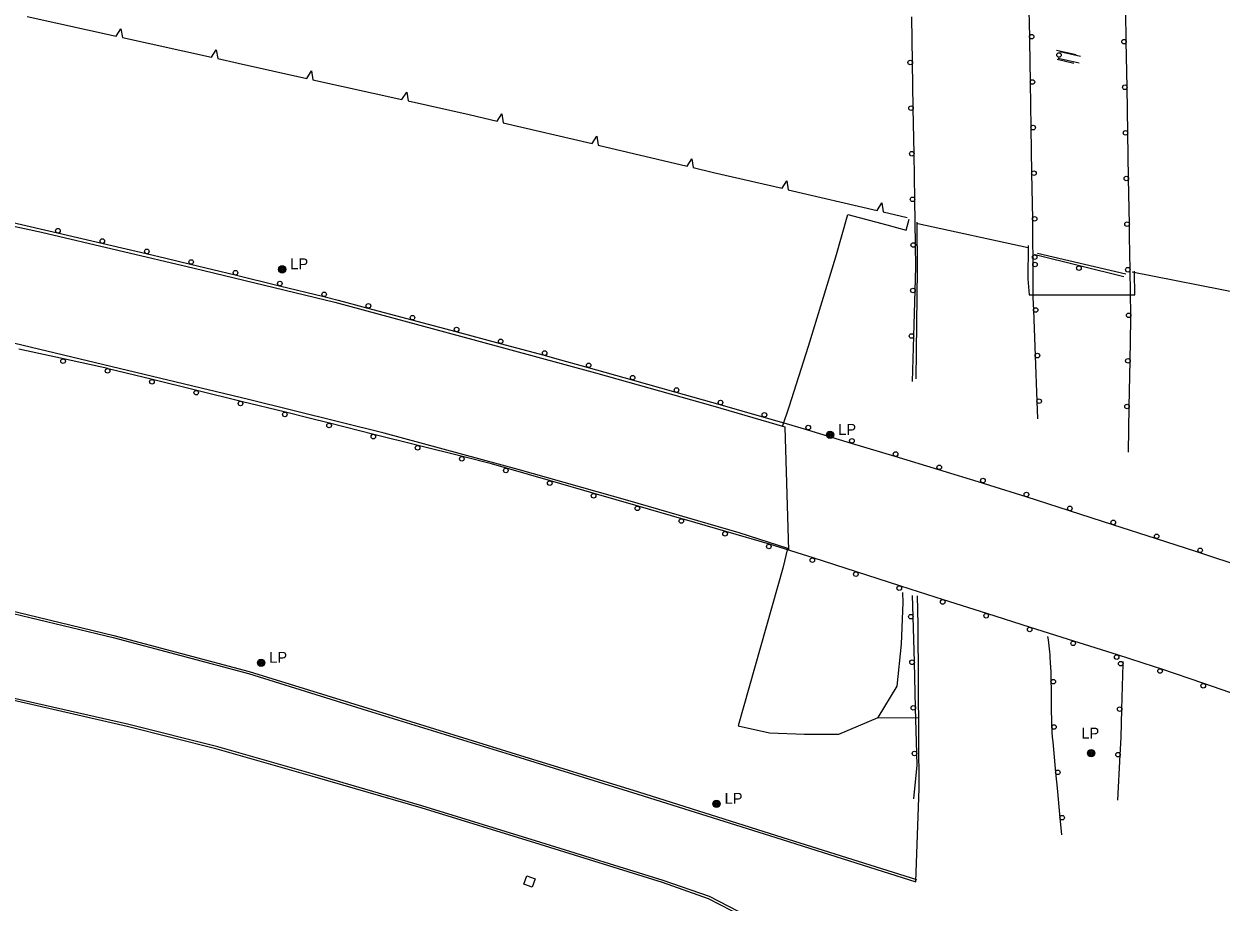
# Model space of a CAD drawing. Extents: x 2402803 to 2427059, y 6985292 to 6997652.
# Drawn here: x 2413911 to 2414436, y 6991229 to 6991614 of the extents above; entities that cross this region are included whole.
import ezdxf

# ---------------------------------------------------------------- set-up
doc = ezdxf.new("R2010")
doc.units = 0
for name, color, linetype in [('p_drainage riprap', 7, 'Continuous'), ('p_dtm retaining wall', 7, 'Continuous'), ('p_dtm sidewalk', 7, 'Continuous'), ('p_road - paved curb', 7, 'Continuous'), ('p_road bridge end', 7, 'Continuous'), ('p_road conc barrier', 7, 'Continuous'), ('p_road guard rails', 7, 'Continuous'), ('p_utility manhole', 7, 'Continuous')]:
    doc.layers.add(name, color=color, linetype=linetype)

msp = doc.modelspace()

# ---------------------------------------------------------------- linework, layer by layer
at = {"layer": 'p_drainage riprap'}
for points in [[(2414243.49, 6991437.79), (2414246.43, 6991446.34), (2414254.83, 6991472.89), (2414266.9, 6991512.05), (2414272.09, 6991530.62), (2414289.18, 6991526.08), (2414297.66, 6991523.82), (2414298.92, 6991528.58)], [(2414245.7, 6991384.28), (2414243.6, 6991375.68), (2414224.09, 6991306.43), (2414237.72, 6991303.37), (2414253.14, 6991302.87), (2414268.2, 6991302.82), (2414285.44, 6991310.17), (2414293.76, 6991323.88), (2414295.59, 6991342.27), (2414296.28, 6991360.5), (2414296.14, 6991364.88)]]:
    msp.add_lwpolyline(points, dxfattribs=at)
at = {"layer": 'p_dtm retaining wall'}
for p, q in [((2413912.38, 6991617.49), (2413951.44, 6991608.87)), ((2413954.15, 6991608.27), (2413993.21, 6991599.66)), ((2414037.66, 6991589.76), (2414076.69, 6991581.04)), ((2414121.09, 6991570.92), (2414160.02, 6991561.73)), ((2414162.71, 6991561.09), (2414201.63, 6991551.89)), ((2414245.98, 6991541.54), (2414284.94, 6991532.48)), ((2414287.64, 6991531.85), (2414298.12, 6991529.41)), ((2414355.29, 6991513.78), (2414393.94, 6991504.71))]:
    msp.add_line(p, q, dxfattribs=at)
for points in [[(2413951.44, 6991608.87), (2413953.51, 6991612.13), (2413954.15, 6991608.27)], [(2413993.21, 6991599.66), (2413995.28, 6991602.92), (2413995.91, 6991599.06)], [(2413995.91, 6991599.06), (2414004.92, 6991597.07), (2414034.95, 6991590.36)], [(2414034.95, 6991590.36), (2414037.03, 6991593.62), (2414037.66, 6991589.76)], [(2414076.69, 6991581.04), (2414078.77, 6991584.29), (2414079.4, 6991580.43)], [(2414079.4, 6991580.43), (2414106.13, 6991574.46), (2414118.4, 6991571.56)], [(2414118.4, 6991571.56), (2414120.52, 6991574.79), (2414121.09, 6991570.92)], [(2414160.02, 6991561.73), (2414162.14, 6991564.96), (2414162.71, 6991561.09)], [(2414201.63, 6991551.89), (2414203.75, 6991555.12), (2414204.33, 6991551.26)], [(2414204.33, 6991551.26), (2414213.28, 6991549.14), (2414243.28, 6991542.16)], [(2414243.28, 6991542.16), (2414245.39, 6991545.4), (2414245.98, 6991541.54)], [(2414284.94, 6991532.48), (2414287.05, 6991535.71), (2414287.64, 6991531.85)]]:
    msp.add_lwpolyline(points, dxfattribs=at)
at = {"layer": 'p_dtm sidewalk'}
msp.add_lwpolyline([(2414285.33, 6991310.12), (2414303.18, 6991309.97)], dxfattribs=at)
at = {"layer": 'p_road - paved curb'}
for points in [[(2413453.34, 6991608.46), (2413509.85, 6991599.67), (2413578.7, 6991589.29), (2413645.86, 6991577.8), (2413715.9, 6991564.99), (2413780.65, 6991551.96), (2413855.53, 6991536.52), (2413918.66, 6991522.88), (2413985.54, 6991507.12), (2414047.19, 6991492.25), (2414109.4, 6991475.44), (2414161.57, 6991461.23), (2414212.88, 6991446.72), (2414244.43, 6991437.52)], [(2414363.5, 6991602.67), (2414372.16, 6991600.87)], [(2414371.2, 6991596.84), (2414363.78, 6991598.66)], [(2414245.83, 6991384.24), (2414224.52, 6991391.1), (2414175.69, 6991405.24), (2414127.62, 6991418.9), (2414068.94, 6991434.75), (2414009.43, 6991449.6), (2413956.34, 6991462.24), (2413903.4, 6991474.96), (2413851.74, 6991485.33), (2413797.83, 6991495.68), (2413736.61, 6991506.25), (2413672.73, 6991516.4), (2413613.14, 6991524.23), (2413535.08, 6991532.86), (2413481.44, 6991537), (2413453.89, 6991539.47)], [(2414302.11, 6991458.63), (2414302.57, 6991506.69), (2414302.45, 6991527.35)], [(2414351.14, 6991517.03), (2414351.03, 6991502.5), (2414351.6, 6991495.39), (2414373.91, 6991495.43), (2414397.85, 6991495.5), (2414397.79, 6991505.37), (2414397.78, 6991505.78)], [(2413454.02, 6991406.53), (2413496.39, 6991406.37), (2413542.63, 6991405.58), (2413589.38, 6991402.88), (2413647.61, 6991398.85), (2413698.58, 6991392.94), (2413761.8, 6991384.22), (2413820.56, 6991374.6), (2413884.46, 6991361.97), (2413950.32, 6991346.15), (2414009.68, 6991330.33), (2414061.69, 6991314.17), (2414124.33, 6991294.84), (2414180.4, 6991277.52), (2414240.81, 6991258.42), (2414302.17, 6991239.11)], [(2413454.02, 6991405.53), (2413496.38, 6991405.37), (2413542.59, 6991404.58), (2413589.32, 6991401.88), (2413647.52, 6991397.85), (2413698.45, 6991391.95), (2413761.65, 6991383.23), (2413820.38, 6991373.62), (2413884.25, 6991360.99), (2413950.07, 6991345.18), (2414009.4, 6991329.37), (2414061.39, 6991313.21), (2414124.04, 6991293.88), (2414180.1, 6991276.57), (2414240.51, 6991257.47), (2414301.87, 6991238.16)], [(2414277.03, 6991186.65), (2414260.39, 6991202.15), (2414237.15, 6991218.35), (2414211.46, 6991231.59), (2414191.18, 6991238.74), (2414137.57, 6991255.4), (2414085.36, 6991271.45), (2414038.86, 6991284.99), (2413995.91, 6991297.26), (2413956.43, 6991307.23), (2413906.16, 6991318.65), (2413847, 6991330.36), (2413820.95, 6991334.68), (2413796.72, 6991338.96), (2413745.99, 6991346.15), (2413683.54, 6991352.92), (2413629.83, 6991356.54), (2413587.38, 6991358.99), (2413519.22, 6991360.65), (2413455.96, 6991360.73)], [(2414301.87, 6991238.16), (2414303.39, 6991279.16), (2414303.25, 6991300.81), (2414302.88, 6991350.73), (2414302.65, 6991363.5)], [(2414276.35, 6991185.92), (2414259.76, 6991201.37), (2414236.63, 6991217.49), (2414211.06, 6991230.67), (2414190.87, 6991237.79), (2414137.27, 6991254.44), (2414085.07, 6991270.49), (2414038.58, 6991284.03), (2413995.65, 6991296.29), (2413956.2, 6991306.26), (2413905.95, 6991317.67), (2413846.82, 6991329.38), (2413820.78, 6991333.69), (2413817.11, 6991334.34)]]:
    msp.add_lwpolyline(points, dxfattribs=at)
at = {"layer": 'p_road bridge end'}
for points in [[(2414302.75, 6991526.73), (2414351.16, 6991516.24)], [(2414396.66, 6991505.5), (2414445.67, 6991495.81)], [(2414244.42, 6991437.36), (2414246.08, 6991383.47)]]:
    msp.add_lwpolyline(points, dxfattribs=at)
msp.add_lwpolyline([(2414135.03, 6991239.48), (2414133.71, 6991235.77), (2414130.13, 6991237.04), (2414131.45, 6991240.75)], close=True, dxfattribs=at)
at = {"layer": 'p_road conc barrier'}
for p, q in [((2414364.96, 6991602.07), (2414374.13, 6991600.02)), ((2414364.31, 6991599.14), (2414373.48, 6991597.09))]:
    msp.add_line(p, q, dxfattribs=at)
msp.add_circle((2414364.63, 6991600.6), 1, dxfattribs=at)
at = {"layer": 'p_road guard rails'}
for p, q in [((2414351.24, 6991628.59), (2414351.67, 6991608.59)), ((2414300.45, 6991597.31), (2414300.12, 6991617.31)), ((2414394.49, 6991586.45), (2414394.16, 6991606.45)), ((2414300.78, 6991577.32), (2414300.45, 6991597.31)), ((2414352.01, 6991588.74), (2414352.33, 6991568.75)), ((2414394.82, 6991566.46), (2414394.49, 6991586.45)), ((2414301.12, 6991557.32), (2414300.78, 6991577.32)), ((2414352.33, 6991568.75), (2414352.65, 6991548.75)), ((2414395.16, 6991546.46), (2414394.82, 6991566.46)), ((2414301.45, 6991537.32), (2414301.12, 6991557.32)), ((2414352.65, 6991548.75), (2414352.97, 6991528.75)), ((2414395.49, 6991526.46), (2414395.16, 6991546.46)), ((2414301.78, 6991517.33), (2414301.45, 6991537.32)), ((2413906.19, 6991527.12), (2413925.66, 6991522.58)), ((2413925.66, 6991522.58), (2413945.14, 6991518.04)), ((2413945.14, 6991518.04), (2413964.61, 6991513.5)), ((2414354.21, 6991512.95), (2414353.94, 6991513.02)), ((2414373.62, 6991508.13), (2414354.21, 6991512.95)), ((2413984.06, 6991508.86), (2414003.5, 6991504.14)), ((2414393.03, 6991503.3), (2414373.62, 6991508.13)), ((2414396.17, 6991486.47), (2414395.83, 6991506.47)), ((2414003.5, 6991504.14), (2414022.93, 6991499.43)), ((2414022.93, 6991499.43), (2414042.37, 6991494.71)), ((2414301.01, 6991477.37), (2414301.62, 6991497.34)), ((2414061.72, 6991489.67), (2414081.04, 6991484.49)), ((2414353.44, 6991488.76), (2414354.18, 6991468.77)), ((2414081.04, 6991484.49), (2414100.35, 6991479.3)), ((2414100.35, 6991479.3), (2414119.67, 6991474.12)), ((2414300.39, 6991457.39), (2414301.01, 6991477.37)), ((2413928.36, 6991467.34), (2413908.82, 6991471.6)), ((2414119.67, 6991474.12), (2414138.99, 6991468.93)), ((2414354.18, 6991468.77), (2414354.93, 6991448.78)), ((2414395.47, 6991446.48), (2414395.85, 6991466.47)), ((2413967.31, 6991458.3), (2413947.9, 6991463.07)), ((2414158.25, 6991463.57), (2414177.5, 6991458.14)), ((2413986.73, 6991453.52), (2413967.31, 6991458.3)), ((2414177.5, 6991458.14), (2414196.75, 6991452.72)), ((2414006.15, 6991448.75), (2413986.73, 6991453.52)), ((2414025.57, 6991443.98), (2414006.15, 6991448.75)), ((2414196.75, 6991452.72), (2414216, 6991447.3)), ((2414354.93, 6991448.78), (2414355.22, 6991441.06)), ((2414216, 6991447.3), (2414235.25, 6991441.88)), ((2414395.09, 6991426.48), (2414395.47, 6991446.48)), ((2414064.37, 6991434.27), (2414044.98, 6991439.15)), ((2414083.77, 6991429.38), (2414064.37, 6991434.27)), ((2414254.46, 6991436.29), (2414273.59, 6991430.47)), ((2414103.16, 6991424.5), (2414083.77, 6991429.38)), ((2414273.59, 6991430.47), (2414292.73, 6991424.66)), ((2414292.73, 6991424.66), (2414311.87, 6991418.85)), ((2414141.72, 6991413.86), (2414122.5, 6991419.39)), ((2414311.87, 6991418.85), (2414331.01, 6991413.04)), ((2414160.94, 6991408.32), (2414141.72, 6991413.86)), ((2414180.15, 6991402.79), (2414160.94, 6991408.32)), ((2414350.06, 6991406.97), (2414369.09, 6991400.85)), ((2414199.37, 6991397.25), (2414180.15, 6991402.79)), ((2414369.09, 6991400.85), (2414388.13, 6991394.72)), ((2414237.78, 6991386.07), (2414218.58, 6991391.67)), ((2414388.13, 6991394.72), (2414407.17, 6991388.6)), ((2414426.2, 6991382.46), (2414445.18, 6991376.2)), ((2414275.9, 6991373.95), (2414256.86, 6991380.08)), ((2414294.93, 6991367.83), (2414275.9, 6991373.95)), ((2414300.72, 6991354.38), (2414300.47, 6991363.56)), ((2414333.05, 6991355.71), (2414313.99, 6991361.76)), ((2414301.26, 6991334.38), (2414300.72, 6991354.38)), ((2414352.11, 6991349.67), (2414333.05, 6991355.71)), ((2414371.18, 6991343.62), (2414352.11, 6991349.67)), ((2414390.24, 6991337.57), (2414371.18, 6991343.62)), ((2414301.79, 6991314.39), (2414301.26, 6991334.38)), ((2414392.22, 6991313.75), (2414392.71, 6991333.74)), ((2414392.71, 6991333.74), (2414392.74, 6991334.75)), ((2414428.19, 6991325), (2414409.28, 6991331.46)), ((2414447.11, 6991318.54), (2414428.19, 6991325)), ((2414302.33, 6991294.4), (2414301.79, 6991314.39)), ((2414390.47, 6991273.87), (2414391.51, 6991293.79)), ((2414365.03, 6991266.12), (2414365.73, 6991258.69))]:
    msp.add_line(p, q, dxfattribs=at)
for points in [[(2414394.16, 6991606.45), (2414394.12, 6991608.76), (2414393.81, 6991626.45)], [(2414351.67, 6991608.59), (2414351.71, 6991606.66), (2414351.73, 6991606.69), (2414352.01, 6991588.74)], [(2414352.97, 6991528.75), (2414353.08, 6991521.67), (2414353.15, 6991508.75)], [(2414395.83, 6991506.47), (2414395.58, 6991520.97), (2414395.49, 6991526.46)], [(2414301.62, 6991497.34), (2414301.94, 6991507.66), (2414301.78, 6991517.33)], [(2413964.61, 6991513.5), (2413973.17, 6991511.51), (2413984.06, 6991508.86)], [(2414353.15, 6991508.75), (2414353.23, 6991494.29), (2414353.44, 6991488.76)], [(2414042.37, 6991494.71), (2414048.69, 6991493.17), (2414061.72, 6991489.67)], [(2414395.85, 6991466.47), (2414396.2, 6991484.53), (2414396.17, 6991486.47)], [(2413947.9, 6991463.07), (2413947.82, 6991463.09), (2413928.36, 6991467.34)], [(2414138.99, 6991468.93), (2414143.47, 6991467.73), (2414158.25, 6991463.57)], [(2414044.98, 6991439.15), (2414035.98, 6991441.42), (2414025.57, 6991443.98)], [(2414235.25, 6991441.88), (2414246.14, 6991438.81), (2414254.46, 6991436.29)], [(2414122.5, 6991419.39), (2414115.95, 6991421.28), (2414103.16, 6991424.5)], [(2414331.01, 6991413.04), (2414334.21, 6991412.07), (2414350.06, 6991406.97)], [(2414218.58, 6991391.67), (2414200.57, 6991396.91), (2414199.37, 6991397.25)], [(2414256.86, 6991380.08), (2414242.43, 6991384.72), (2414237.78, 6991386.07)], [(2414407.17, 6991388.6), (2414424.48, 6991383.03), (2414426.2, 6991382.46)], [(2414313.99, 6991361.76), (2414299.37, 6991366.4), (2414294.93, 6991367.83)], [(2414359.61, 6991345.7), (2414359.72, 6991344.95), (2414359.84, 6991344.21), (2414360.04, 6991342.84), (2414360.21, 6991341.51), (2414360.36, 6991340.22), (2414360.49, 6991338.97), (2414360.6, 6991337.75), (2414360.7, 6991336.57), (2414360.85, 6991334.27), (2414360.96, 6991332.12), (2414361.04, 6991330.09), (2414361.1, 6991328.18), (2414361.14, 6991326.39), (2414361.14, 6991325.84)], [(2414409.28, 6991331.46), (2414406.51, 6991332.41), (2414390.24, 6991337.57)], [(2414361.14, 6991325.84), (2414361.18, 6991323.03), (2414361.22, 6991317.13), (2414361.27, 6991312.71), (2414361.34, 6991309.39), (2414361.42, 6991306.91), (2414361.47, 6991305.91)], [(2414391.51, 6991293.79), (2414391.91, 6991301.4), (2414392.22, 6991313.75)], [(2414361.47, 6991305.91), (2414361.51, 6991305.05), (2414361.58, 6991303.66), (2414361.72, 6991301.58), (2414361.9, 6991299.5), (2414363.17, 6991286.01)], [(2414301.05, 6991274.47), (2414302.47, 6991289.26), (2414302.33, 6991294.4)], [(2414363.17, 6991286.01), (2414363.81, 6991279.09), (2414365.03, 6991266.12)]]:
    msp.add_lwpolyline(points, dxfattribs=at)
for centre in [(2414352.67, 6991608.62), (2414393.16, 6991606.44), (2414299.45, 6991597.3), (2414353.01, 6991588.76), (2414393.49, 6991586.44), (2414299.78, 6991577.3), (2414353.33, 6991568.76), (2414393.82, 6991566.44), (2414300.12, 6991557.3), (2414353.65, 6991548.76), (2414394.16, 6991546.44), (2414300.45, 6991537.31), (2414353.97, 6991528.77), (2414394.49, 6991526.45), (2413925.89, 6991523.55), (2413945.36, 6991519.02), (2414300.78, 6991517.31), (2413964.84, 6991514.48), (2414353.97, 6991511.98), (2413984.3, 6991509.84), (2414354.15, 6991508.76), (2414373.38, 6991507.16), (2414394.83, 6991506.45), (2414003.73, 6991505.12), (2414023.17, 6991500.4), (2414042.6, 6991495.68), (2414300.62, 6991497.37), (2414061.98, 6991490.64), (2414081.3, 6991485.45), (2414354.44, 6991488.79), (2414395.17, 6991486.45), (2414100.61, 6991480.27), (2414119.93, 6991475.08), (2414300.01, 6991477.4), (2414139.24, 6991469.9), (2414355.18, 6991468.81), (2413928.14, 6991466.36), (2414158.52, 6991464.53), (2414394.85, 6991466.49), (2413947.66, 6991462.1), (2414177.77, 6991459.11), (2413967.08, 6991457.33), (2414197.02, 6991453.68), (2413986.5, 6991452.55), (2414005.91, 6991447.78), (2414216.27, 6991448.26), (2414355.93, 6991448.82), (2414025.33, 6991443.01), (2414235.53, 6991442.84), (2414394.47, 6991446.5), (2414044.74, 6991438.18), (2414254.75, 6991437.24), (2414064.13, 6991433.3), (2414083.52, 6991428.41), (2414273.88, 6991431.43), (2414102.92, 6991423.53), (2414293.02, 6991425.62), (2414122.22, 6991418.43), (2414312.16, 6991419.81), (2414141.44, 6991412.9), (2414331.3, 6991414), (2414160.66, 6991407.36), (2414350.36, 6991407.92), (2414179.88, 6991401.83), (2414369.4, 6991401.8), (2414199.1, 6991396.29), (2414388.44, 6991395.68), (2414218.3, 6991390.71), (2414237.5, 6991385.11), (2414407.47, 6991389.55), (2414426.51, 6991383.41), (2414256.55, 6991379.13), (2414275.59, 6991373), (2414294.63, 6991366.88), (2414313.69, 6991360.81), (2414299.72, 6991354.35), (2414332.75, 6991354.76), (2414351.81, 6991348.71), (2414370.87, 6991342.67), (2414300.26, 6991334.36), (2414389.93, 6991336.62), (2414391.72, 6991333.76), (2414408.95, 6991330.52), (2414362.14, 6991325.86), (2414427.87, 6991324.06), (2414300.79, 6991314.36), (2414391.22, 6991313.77), (2414362.47, 6991305.96), (2414301.33, 6991294.37), (2414390.51, 6991293.84), (2414364.16, 6991286.1), (2414366.03, 6991266.22)]:
    msp.add_circle(centre, 1, dxfattribs=at)
at = {"layer": 'p_utility manhole'}
for centre, radius in [((2414024.14, 6991506.62), 1.6), ((2414024.14, 6991506.62), 1.3), ((2414024.14, 6991506.62), 1), ((2414024.14, 6991506.62), 0.539), ((2414024.14, 6991506.62), 0.192), ((2414264.31, 6991434.06), 1.6), ((2414264.31, 6991434.06), 1.3), ((2414264.31, 6991434.06), 1), ((2414264.31, 6991434.06), 0.539), ((2414264.31, 6991434.06), 0.192), ((2414014.93, 6991334.12), 1.6), ((2414014.93, 6991334.12), 1.3), ((2414014.93, 6991334.12), 1), ((2414014.93, 6991334.12), 0.539), ((2414014.93, 6991334.12), 0.192), ((2414378.72, 6991294.47), 1.6), ((2414378.72, 6991294.47), 1.3), ((2414378.72, 6991294.47), 1), ((2414378.72, 6991294.47), 0.539), ((2414378.72, 6991294.47), 0.192), ((2414214.52, 6991272.3), 1.6), ((2414214.52, 6991272.3), 1.3), ((2414214.52, 6991272.3), 1), ((2414214.52, 6991272.3), 0.539), ((2414214.52, 6991272.3), 0.192)]:
    msp.add_circle(centre, radius, dxfattribs=at)

# ---------------------------------------------------------------- texts
for p in [(2414024.14, 6991506.62), (2414264.31, 6991434.06), (2414014.93, 6991334.12), (2414370.88, 6991300.88), (2414214.52, 6991272.3)]:
    msp.add_text('  LP', height=4.8, dxfattribs=at).set_placement(p)

doc.saveas('drawing.dxf')
